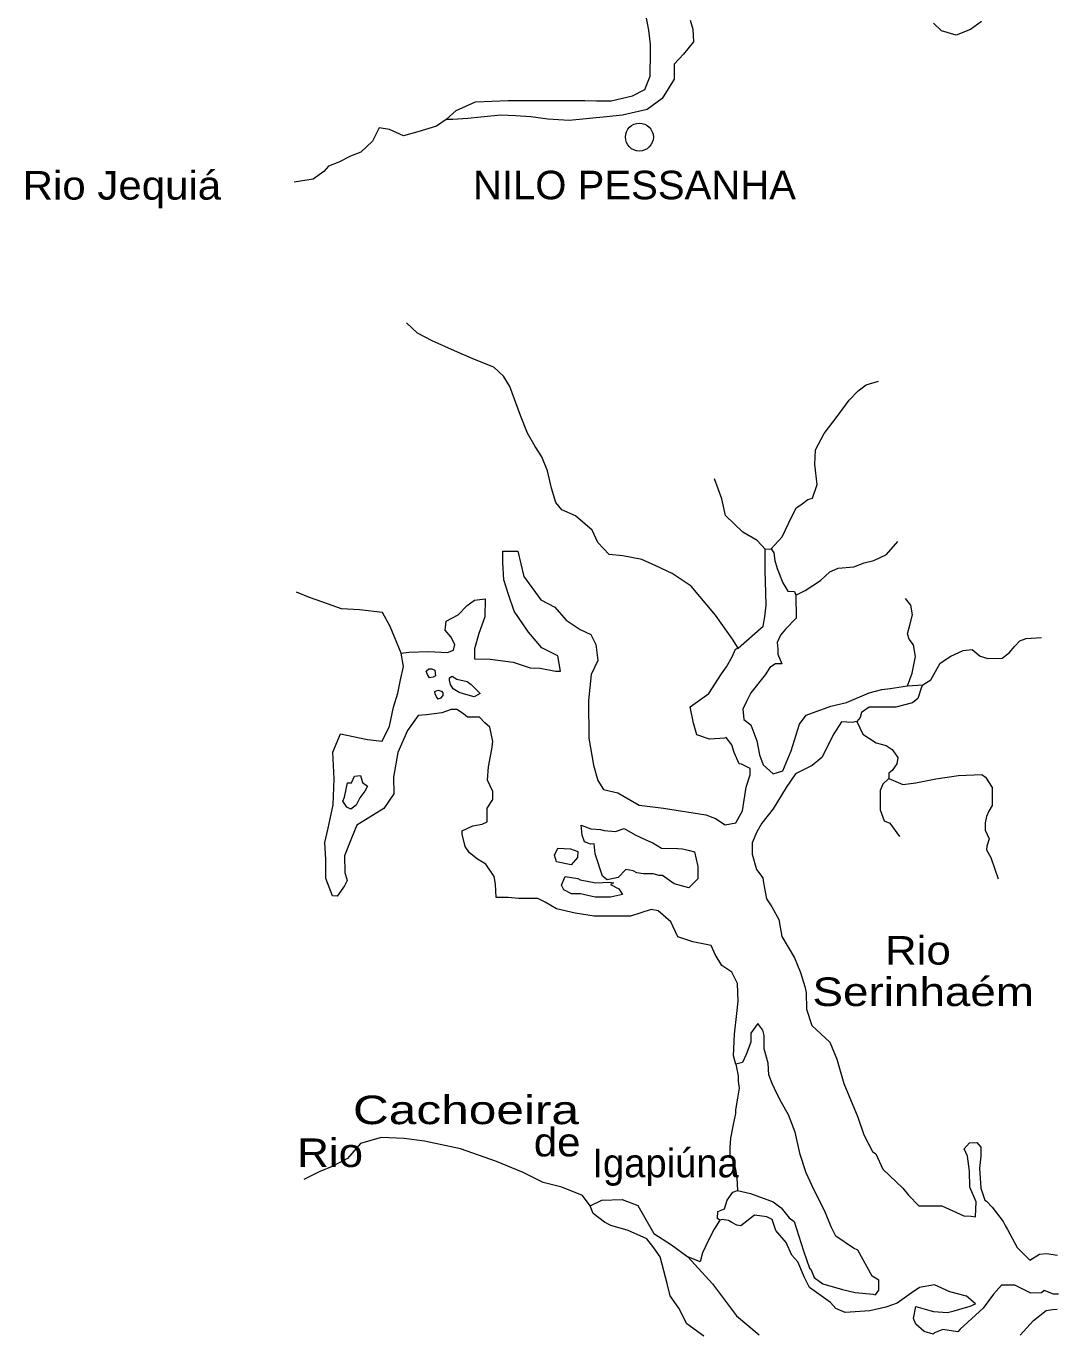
# Model space of a CAD drawing. Extents: x 47169 to 972804, y 7447977 to 9608469.
# Drawn here: x 476028 to 499948, y 8467863 to 8498234 of the extents above; entities that cross this region are included whole.
import ezdxf

# ---------------------------------------------------------------- set-up
doc = ezdxf.new("R2010")
doc.units = 0
doc.header["$LTSCALE"] = 270
doc.layers.add('1', color=7, linetype='Continuous', lineweight=13)
doc.layers.add('2', color=7, linetype='Continuous', lineweight=13)
doc.layers.add('3', color=7, linetype='Continuous')

msp = doc.modelspace()

# ---------------------------------------------------------------- linework, layer by layer
at = {"layer": '1'}
for points in [[(491465.8, 8498375.8), (491530.8, 8498165.8), (491541.7, 8497867.2), (491314.6, 8497579.5), (491098.3, 8497347.2), (491098.4, 8497004.4), (490817.3, 8496550.8), (490471.2, 8496296.4), (489897.9, 8496163.4), (489519.3, 8496130.1), (488653.9, 8496041.3), (488156.3, 8496074.2), (487766.9, 8496129.3), (487409.9, 8496151.3), (487063.7, 8496162.2), (486598.5, 8496117.7), (486295.7, 8496084.4), (485949.5, 8496062.1), (485798, 8496062), (486025.1, 8496272.3), (486479.4, 8496471.6), (487236.6, 8496505.1), (487669.3, 8496505.3), (488026.3, 8496505.5), (488707.8, 8496505.8), (489021.6, 8496505.9), (489292, 8496495), (489627.4, 8496495.1), (490125, 8496617), (490417, 8496760.8), (490535.9, 8497070.5), (490546.5, 8497634.6), (490546.4, 8497811.5), (490503, 8498143.3), (490427.2, 8498541.4)], [(498238.3, 8498344), (497989.5, 8498156), (497654.2, 8498023.2), (497308, 8498122.7), (497124, 8498299.7)], [(485798, 8496062), (485571, 8495907.1), (485138.3, 8495774.1), (484803, 8495685.4), (484478.4, 8495829), (484240.4, 8495873.1), (484078.3, 8495563.4), (483808, 8495308.8), (483570.1, 8495209.1), (483299.8, 8495076.3), (483061.8, 8494976.6), (482953.7, 8494854.8), (482705, 8494677.7), (482261.6, 8494611.1)], [(492584.3, 8483777.8), (492454.5, 8483987.9), (492054.2, 8484540.8), (491491.7, 8485215.2), (491048.3, 8485513.7), (490669.7, 8485690.5), (490345.3, 8485834.2), (489901.9, 8485922.5), (489588.3, 8485955.5), (489317.8, 8486231.9), (489187.9, 8486519.4), (488798.5, 8486851), (488484.8, 8486994.6), (488344.2, 8487160.5), (488246.7, 8487492.2), (488149.2, 8487901.4), (488019.3, 8488222), (487867.8, 8488465.3), (487683.8, 8488774.8), (487521.3, 8489184), (487272.3, 8489858.5), (487131.5, 8490101.7), (486904.3, 8490311.7), (486450, 8490488.4), (485984.8, 8490687.3), (485465.5, 8490919.2), (485130.1, 8491096), (484870.4, 8491339.1)], [(493351.4, 8486089.5), (493610.8, 8486366), (493762.2, 8486686.8), (493935.1, 8487040.7), (494043.2, 8487107.1), (494205.4, 8487228.8), (494313.5, 8487262), (494421.6, 8487582.7), (494367.5, 8488047.2), (494378.2, 8488390.1), (494583.6, 8488766.1), (494886.3, 8489164.3), (495167.5, 8489540.4), (495372.9, 8489761.6), (495556.7, 8489894.4), (495848.7, 8489982.9)], [(493210.8, 8486078.4), (493026.9, 8486277.4), (492691.6, 8486476.4), (492291.4, 8486863.3), (492204.8, 8487250.4), (492031.6, 8487714.8)], [(489318.9, 8483489.2), (489167.7, 8483168.4), (489103.1, 8482560.1), (489114.2, 8481686.4), (489222.6, 8481056), (489320.1, 8480702.2), (489449.9, 8480492.1), (489785.1, 8480414.8), (490282.5, 8480127.5), (490844.7, 8480061.3), (491828.6, 8479906.8), (492055.7, 8479818.4), (492282.7, 8479674.7), (492531.4, 8479719), (492682.6, 8479995.5), (492769, 8480548.5), (492866.2, 8480836.1), (492866.2, 8480979.9), (492660.7, 8481079.3), (492606.7, 8481090.4), (492487.7, 8481355.8), (492433.5, 8481532.7), (492303.7, 8481698.6), (492271.3, 8481687.5), (491914.5, 8481665.3), (491622.6, 8481764.7), (491546.8, 8482030.1), (491471, 8482417.2), (491903.4, 8482727), (492195.2, 8483180.5), (492314.1, 8483346.4), (492443.8, 8483578.7), (492519.4, 8483755.7), (492584.3, 8483777.8), (492908.6, 8484065.5), (493168, 8484286.7), (493200.4, 8484507.9), (493232.8, 8484773.4), (493221.8, 8485326.3), (493210.9, 8485569.6), (493210.9, 8485790.8), (493210.8, 8486078.4), (493351.4, 8486089.5), (493416.3, 8485989.9), (493438, 8485813), (493492.1, 8485625), (493621.9, 8485293.2), (493740.9, 8485105.3), (493892.3, 8485094.2), (493924.8, 8485005.8), (493935.7, 8484474.9), (493687.1, 8484220.5), (493568.2, 8484076.7), (493492.5, 8483910.8), (493503.4, 8483756), (493503.4, 8483634.3), (493600.8, 8483413.1), (493449.4, 8483413.1), (493319.7, 8483324.6), (493211.6, 8483158.7), (492876.5, 8482738.3), (492779.2, 8482539.2), (492692.8, 8482362.2), (492714.5, 8482118.9), (492876.7, 8481997.3), (493017.4, 8481621.4), (493082.3, 8481300.7), (493168.9, 8481068.4), (493396, 8480858.4), (493623, 8480924.8), (493817.5, 8481389.3), (494012, 8482008.7), (494163.3, 8482218.9), (494736.3, 8482429.1), (495103.9, 8482517.7), (495633.6, 8482738.9), (495925.5, 8482816.4), (496120.2, 8482838.6), (496520.2, 8482905), (496877, 8482927.1), (496844.6, 8482871.8), (496758.1, 8482606.4), (496639.2, 8482506.8), (496250, 8482407.2), (495958, 8482407.2), (495633.7, 8482407.2), (495449.9, 8482285.5), (495417.5, 8482163.8), (495341.8, 8482075.3), (495233.7, 8482053.2), (494985, 8482064.2), (494812.1, 8481787.7), (494531.1, 8481234.6), (494304.1, 8481046.6), (493914.9, 8480858.5), (493698.8, 8480537.7), (493396.2, 8480040), (493136.8, 8479708.1), (493017.9, 8479509), (492909.9, 8479254.6), (492910, 8478989.2)], [(493924.8, 8485005.8), (494141, 8485116.4), (494497.8, 8485348.7), (494714, 8485547.8), (494908.6, 8485636.4), (495276.3, 8485669.6), (495514.2, 8485758.1), (495741.2, 8485813.5), (496033.2, 8485957.3), (496292.7, 8486255.9)], [(487678, 8477958.7), (487472.6, 8477958.6), (487234.8, 8477980.6), (486953.7, 8477980.5), (486942.8, 8478290.1), (486910.2, 8478467.1), (486715.5, 8478754.5), (486520.9, 8478876.1), (486337, 8479019.7), (486239.6, 8479163.5), (486163.8, 8479451), (486163.8, 8479528.4), (486412.4, 8479650.2), (486628.6, 8479683.5), (486747.5, 8479738.8), (486747.4, 8479805.2), (486747.3, 8480059.6), (486876.9, 8480258.7), (486876.8, 8480446.7), (486757.8, 8480712.1), (486779.2, 8481021.7), (486854.7, 8481431), (486876.2, 8481607.9), (486811.2, 8481939.7), (486692.2, 8482039.2), (486573.2, 8482171.8), (486292.1, 8482171.7), (486194.8, 8482249), (486043.3, 8482348.5), (485913.6, 8482348.4), (485697.4, 8482270.9), (485340.6, 8482226.4), (485146, 8482215.3), (484897.5, 8481861.2), (484670.8, 8481352.4), (484573.8, 8480777.2), (484574, 8480390.1), (484347.2, 8480047.2), (483720.4, 8479659.7), (483590.9, 8479361), (483429, 8478951.7), (483440, 8478564.6), (483494.2, 8478376.7), (483429.4, 8478254.9), (483256.6, 8478011.5), (483148.5, 8478022.5), (482996.9, 8478420.6), (482996.6, 8478862.9), (482974.7, 8479261.1), (483050.2, 8479592.9), (483168.7, 8480134.9), (483190, 8480743.2), (483157.1, 8481362.5), (483340.7, 8481782.9), (483967.8, 8481650.6), (484303, 8481617.6), (484475.8, 8481960.5), (484572.8, 8482403), (484670, 8482734.8), (484734.7, 8483044.5), (484799.3, 8483354.2), (484745.1, 8483663.8), (484928.9, 8483686.1), (485383, 8483697.4), (485826.4, 8483675.5), (485966.9, 8483730.9), (485999.3, 8483863.6), (485901.9, 8484040.5), (485772, 8484195.3), (485793.5, 8484405.4), (486074.6, 8484549.3), (486279.9, 8484770.6), (486452.9, 8484892.4), (486701.6, 8484925.7), (486691, 8484505.4), (486550.6, 8484118.3), (486453.5, 8483764.3), (486453.6, 8483532.1), (486821.2, 8483521.2), (487351.1, 8483455.1), (487751.2, 8483322.6), (487978.3, 8483311.6), (488335.1, 8483245.4), (488454, 8483245.5), (488389, 8483599.3), (488021.3, 8483787.2), (487707.5, 8484152), (487372.1, 8484638.5), (487242.2, 8485025.5), (487133.9, 8485368.3), (487112, 8485766.4), (487111.9, 8486031.8), (487458, 8486032), (487598.8, 8485445.9), (487999.2, 8484904.2), (488323.6, 8484727.4), (488583.3, 8484428.9), (488907.8, 8484207.8), (489156.5, 8484097.4), (489275.5, 8483865.2), (489318.9, 8483489.2)], [(484745.1, 8483663.8), (484496, 8484283), (484312, 8484603.6), (483782.2, 8484669.7), (483360.4, 8484691.5), (482927.8, 8484846.1), (482614.1, 8484956.5), (482311.3, 8485077.9)], [(496520.2, 8482905), (496628.3, 8483192.5), (496703.9, 8483579.6), (496660.7, 8483856.1), (496563.3, 8483988.8), (496520, 8484110.4), (496574.1, 8484309.5), (496638.9, 8484552.8), (496595.7, 8484774), (496476.7, 8484928.8)], [(496877, 8482927.1), (497060.8, 8483037.7), (497277, 8483424.8), (497525.7, 8483590.8), (497817.6, 8483723.5), (498023.1, 8483745.6), (498206.9, 8483590.8), (498390.7, 8483535.5), (498725.9, 8483546.6), (498888.1, 8483668.3), (499017.8, 8483823.1), (499136.8, 8483944.8), (499277.3, 8484000.1), (499634.2, 8484022.2)], [(495341.8, 8482075.3), (495482.4, 8481776.7), (495796, 8481577.7), (496023, 8481511.4), (496163.6, 8481422.9), (496293.4, 8481234.9), (496271.8, 8481091.2), (496163.7, 8480936.3), (496088, 8480870), (496088, 8480781.5), (496088, 8480748.3), (496412.4, 8480604.6), (496715.1, 8480648.9), (497180, 8480737.4), (497709.8, 8480814.9), (498250.3, 8480837), (498336.8, 8480781.7), (498488.2, 8480538.4), (498488.2, 8480118.2), (498412.5, 8479985.4), (498358.5, 8479863.8), (498326.1, 8479720), (498326.1, 8479543.1), (498423.4, 8479344), (498369.4, 8479178.1), (498358.5, 8479089.6), (498455.9, 8478912.7), (498628.9, 8478415)], [(496088, 8480748.3), (495947.5, 8480615.6), (495882.7, 8480471.8), (495882.7, 8480018.3), (495980.1, 8479764), (496109.8, 8479708.7), (496336.9, 8479399.1)], [(492910, 8478989.2), (493007.4, 8478635.3), (493158.7, 8478436.3), (493169.6, 8478325.7), (493245.4, 8477949.7), (493364.3, 8477761.7), (493526.5, 8477474.2), (493602.3, 8477076.1), (493894.3, 8476578.5), (494034.9, 8476235.7), (494132.3, 8475915), (494164.7, 8475771.2), (494175.6, 8475384.1), (494294.6, 8475008.1), (494716.2, 8474621.1), (494878.4, 8474223), (495040.7, 8473659), (495365.1, 8472873.8), (495505.7, 8472464.7), (495711.1, 8472077.6), (495786.7, 8472022.3), (495948.9, 8471668.5), (496413.7, 8471226.1), (496543.4, 8471060.3), (496781.2, 8470817), (497073, 8470817), (497321.6, 8470817.1), (497829.5, 8470584.8), (498002.5, 8470573.8), (498099.7, 8470562.8), (498121.3, 8470905.6), (497970, 8471248.4), (497959.1, 8471624.4), (497915.9, 8471967.3), (497840.2, 8472144.2), (497959.1, 8472277), (498132, 8472288), (498229.3, 8472177.4), (498229.3, 8471967.3), (498196.9, 8471690.8), (498229.4, 8471226.3), (498315.8, 8470949.8), (498359.1, 8470927.7), (498488.8, 8470784), (498748.2, 8470452.2), (498802.2, 8470341.6), (498845.4, 8470264.2), (499072.4, 8469843.9), (499364.2, 8469556.4), (499591.1, 8469689.1), (499753.2, 8469711.2), (500012.6, 8469667)], [(497127.3, 8468361.8), (497451.5, 8468339.7), (497602.8, 8468372.9), (497981, 8468483.6), (498099.9, 8468538.9), (497894.5, 8468715.8), (497505.5, 8468815.3), (497148.9, 8468981.2), (496803, 8468914.8), (496608.5, 8468782), (496392.5, 8468627.2), (496284.4, 8468549.7), (496014.2, 8468461.2), (495646.8, 8468372.7), (495074.1, 8468339.4), (494858, 8468427.8), (494728.3, 8468571.6), (494241.9, 8468914.3), (494123, 8469146.5), (493971.6, 8469511.5), (493831.1, 8469666.3), (493701.3, 8469964.8), (493463.5, 8470241.3), (493377, 8470495.6), (493247.3, 8470561.9), (492966.3, 8470595.1), (492642.1, 8470351.7), (492555.7, 8470362.7), (492436.8, 8470429), (492361.1, 8470473.2), (492209.8, 8470495.3), (492155.8, 8470484.2), (492101.7, 8470517.4), (492112.5, 8470683.3), (492263.8, 8470749.7), (492328.5, 8470948.8), (492458.2, 8471136.8), (492566.2, 8471170), (492868.9, 8471103.8), (493398.5, 8470904.8), (493582.2, 8470772.2), (493766, 8470539.9), (493884.9, 8470451.5), (494101.2, 8469765.9), (494241.8, 8469367.8), (494274.2, 8469345.6), (494349.9, 8469146.6), (494555.3, 8469002.8), (495009.2, 8468870.2), (495301, 8468803.9), (495722.4, 8468759.8), (495776.5, 8468748.7), (495852.1, 8468859.3), (495852.1, 8469091.6), (495700.7, 8469180), (495365.6, 8469788.2), (495268.4, 8469832.5), (494857.6, 8470108.9), (494749.5, 8470330), (494598.2, 8470695), (494349.5, 8471181.5), (494165.7, 8471579.6), (494025.1, 8472010.9), (493906, 8472530.7), (493754.7, 8472928.8), (493592.5, 8473216.3), (493484.3, 8473426.4), (493376.2, 8473658.6), (493300.5, 8473857.7), (493278.8, 8474134.2), (493192.2, 8474465.9), (493192.1, 8474775.6), (493159.7, 8474897.2), (493040.7, 8475052.1), (492878.7, 8474830.8), (492878.7, 8474620.7), (492770.7, 8474333.1), (492684.3, 8474145.1), (492533, 8474111.8), (492478.9, 8474299.8), (492500.4, 8474808.6), (492554.3, 8475284.2), (492586.6, 8475571.7), (492564.9, 8475980.9), (492435.1, 8476246.3), (492208, 8476401.1), (492045.8, 8476655.4), (491959.3, 8476865.5), (491526.8, 8476953.8), (491180.9, 8477064.3), (491018.6, 8477418.2), (490726.7, 8477672.4), (490564.5, 8477705.5), (490078.1, 8477550.5), (489710.5, 8477550.4), (489234.9, 8477550.2), (488791.7, 8477616.4), (488359.2, 8477715.7), (488099.7, 8477870.4), (487926.7, 8477958.8), (487678, 8477958.7)], [(492533, 8474111.8), (492587.1, 8473835.4), (492587.1, 8473713.7), (492608.8, 8473547.8), (492565.6, 8473315.6), (492522.5, 8473050.1), (492522.5, 8472961.7), (492468.5, 8472707.3), (492403.8, 8472386.5), (492393, 8472176.4), (492393.1, 8472010.5), (492468.8, 8471855.7), (492490.4, 8471778.3), (492522.9, 8471667.7), (492555.4, 8471468.6), (492566.2, 8471170)], [(489140.4, 8470814.9), (488967.4, 8471058.2), (488481, 8471245.9), (488048.6, 8471356.3), (487583.8, 8471588.4), (486967.6, 8471842.4), (486124.5, 8472140.6), (485292.2, 8472317.1), (484816.6, 8472383.2), (484287, 8472405), (483800.7, 8472260.9), (483498.3, 8471917.9), (483141.7, 8471729.6), (482839.2, 8471607.8), (482482.7, 8471430.6)], [(491789.2, 8467785.6), (491389.3, 8468073), (491205.4, 8468437.9), (491000, 8468725.4), (490935.1, 8469012.9), (490772.8, 8469632.2), (490621.4, 8469842.2), (490459.2, 8470052.3), (490026.8, 8470240.2), (489626.9, 8470361.7), (489475.6, 8470439), (489216.2, 8470638), (489140.4, 8470814.9), (489410.6, 8470947.7), (489886.1, 8470959), (490253.6, 8470826.4), (490621.3, 8470174), (491032, 8469908.8), (491410.4, 8469632.4), (491983.3, 8469002.2), (492545.5, 8468261.4), (493075.1, 8467819.1)], [(492155.8, 8470484.2), (492026.1, 8470274.1), (491896.5, 8470019.6), (491756.2, 8469721), (491702.2, 8469510.8), (491410.4, 8469632.4)], [(500034.2, 8468760.1), (499915.3, 8468760.1), (499699.2, 8468848.6), (499634.4, 8468793.3), (499385.8, 8468782.2), (499018.4, 8468970.2), (498705, 8468970.2), (498521.3, 8468760.1), (498283.6, 8468439.3), (497743.3, 8467952.7), (497689.3, 8467886.3), (497343.5, 8467941.6), (497149, 8467864.1), (497116.6, 8467831), (496911.2, 8467897.3), (496716.7, 8468063.2), (496662.7, 8468195.9), (496716.7, 8468472.4), (497040.9, 8468383.9), (497127.3, 8468361.8)], [(499137.3, 8467809), (499450.7, 8468151.8), (499742.4, 8468384.1), (499893.7, 8468406.2), (500001.8, 8468417.3)]]:
    msp.add_lwpolyline(points, dxfattribs=at)
for points in [[(485534.7, 8483266.2), (485545.5, 8483133.4), (485491.5, 8483100.2), (485405, 8483089.1), (485361.7, 8483166.5), (485329.2, 8483243.9), (485394.1, 8483299.2), (485458.9, 8483299.3)], [(486378.2, 8482934.8), (486583.8, 8482724.8), (486443.2, 8482647.3), (486248.6, 8482702.5), (486097.2, 8482746.7), (485956.6, 8482835.1), (485891.6, 8482934.6), (485870, 8483034.1), (485869.9, 8483089.4), (485934.8, 8483122.6), (486043, 8483056.3), (486280.9, 8483001.1)], [(485718.8, 8482735.4), (485718.8, 8482680.1), (485664.8, 8482613.7), (485610.7, 8482591.6), (485567.4, 8482646.8), (485535, 8482713.2), (485534.9, 8482768.5), (485599.8, 8482801.7), (485686.3, 8482779.6)], [(483428.1, 8480312), (483503.6, 8480643.8), (483590, 8480643.9), (483665.6, 8480798.8), (483806.2, 8480821), (483849.5, 8480655.1), (483968.5, 8480566.7), (483903.7, 8480456.1), (483784.9, 8480301.2), (483698.5, 8480124.2), (483579.6, 8480035.6), (483482.3, 8480079.8), (483395.7, 8480223.5)], [(489471.9, 8479541), (489731.4, 8479519), (489936.8, 8479585.4), (490185.5, 8479441.7), (490434.2, 8479320.2), (490596.4, 8479253.9), (490801.8, 8479132.3), (491180.2, 8479121.4), (491288.3, 8479110.3), (491450.5, 8479077.2), (491569.4, 8479044.1), (491645.2, 8478701.3), (491645.3, 8478413.7), (491440, 8478203.5), (491094, 8478302.9), (490823.7, 8478490.9), (490748, 8478490.8), (490607.4, 8478535), (490380.4, 8478534.9), (490229, 8478557), (490142.5, 8478601.2), (489969.6, 8478634.3), (489796.7, 8478446.2), (489537.2, 8478390.8), (489429.1, 8478479.3), (489255.9, 8478999), (489234.2, 8479231.2), (489147.7, 8479220.1), (489007.2, 8479275.4), (488953, 8479430.2), (488931.3, 8479662.4), (489158.4, 8479574.1), (489385.4, 8479563.1)], [(488704.7, 8478744.4), (488358.7, 8478810.6), (488315.4, 8478965.4), (488391, 8479131.3), (488682.9, 8479109.3), (488855.9, 8479054.1), (488845.1, 8478910.3)], [(488910.2, 8478390.6), (489277.8, 8478324.4), (489602.1, 8478335.6), (489688.6, 8478324.5), (489613, 8478280.3), (489807.6, 8478180.8), (489894.1, 8478048.1), (489613.1, 8477992.7), (489256.3, 8477992.6), (489018.5, 8478047.8), (488921.2, 8478069.9), (488856.3, 8478069.8), (488705, 8478069.8), (488532, 8478158.2), (488477.9, 8478268.7), (488564.3, 8478467.8), (488856.2, 8478423.7)]]:
    msp.add_lwpolyline(points, close=True, dxfattribs=at)
at = {"layer": '2'}
msp.add_circle((490287.6, 8495654.8), 324.5, dxfattribs=at)

# ---------------------------------------------------------------- texts
at = {"layer": '3'}
for s, height, width, p in [('Rio Jequiá', 663.9, 1.1, (475948, 8494202.9)), ('NILO PESSANHA', 663.9, 1.05, (486415.8, 8494209.8)), ('Rio ', 663.5, 1.15, (495997.4, 8476422.3)), ('Serinhaém', 663.5, 1.2, (494312.2, 8475459.7)), ('Cachoeira', 663.4, 1.3, (483627.5, 8472714.3)), ('Rio ', 663.4, 1.15, (482331.2, 8471718.1)), ('de', 663.4, 1.1, (487832.2, 8471964.5))]:
    msp.add_text(s, height=height, dxfattribs=dict(at, width=width)).set_placement(p)
msp.add_text('Igapiúna', height=663.4, dxfattribs=at).set_placement((489194.2, 8471478.5))

doc.saveas('drawing.dxf')
